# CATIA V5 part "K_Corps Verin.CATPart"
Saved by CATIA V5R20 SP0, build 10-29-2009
Part number: Corps Verin
Bounding box of the stored display mesh (mm): x 0 to 2, y -10 to 1, z -1 to 1
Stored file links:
  G:\Khaled_CFAO_2011\ST2M\ST2M_GR1\bgaltie\bgaltie\Khaled\CAD_thinkMOTION\K_Corps Verin.CATPart
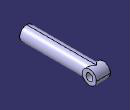
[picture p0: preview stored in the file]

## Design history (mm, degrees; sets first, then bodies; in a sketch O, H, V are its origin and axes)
AxisSystem1: origin (0, 0, 0), X (1, 0, 0), Y (0, 1, 0), Z (0, 0, 1)
Body1 (main body)
  Sketch1 on YZ plane of AxisSystem1, origin (0, 0, 0), H (0, 1, 0), V (0, 0, 1)
    circle A1 centre (0, 0) radius 1
    point P1 (0, 0)
    radius A1 = 1
    coincidence: P1 O
  Pad1: profile Sketch1, direction (1, 0, 0), length 2
  Sketch2 on ZX plane of AxisSystem1, origin (0, 0, 0), H (0, 0, 1), V (1, 0, 0)
    circle A1 centre (0, 1) radius 1
    point P1 (0, 1)
    circle A2 centre (0, 1) radius 0.75
    point P2 (0, 1)
    distance P1 O = 1
    radius A1 = 1
    radius A2 = 0.75
    coincidence: P1 V, P2 P1
  Pad2: profile Sketch2, direction (0, -1, 0), length 10
  Sketch3 on end face of Pad1, origin (2, 0, 0), H (0, 1, 0), V (0, 0, 1)
    point P1 (0, 0)
    reference projected point E1 (0, 0) from vertex [YZ plane of AxisSystem1 | ZX plane of AxisSystem1 | XY plane of AxisSystem1]
    coincidence: P1 E1
  Hole1: placed by Sketch3, at (2, 0, 0) direction (-1, 0, 0), diameter 1, through (limit type 6)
